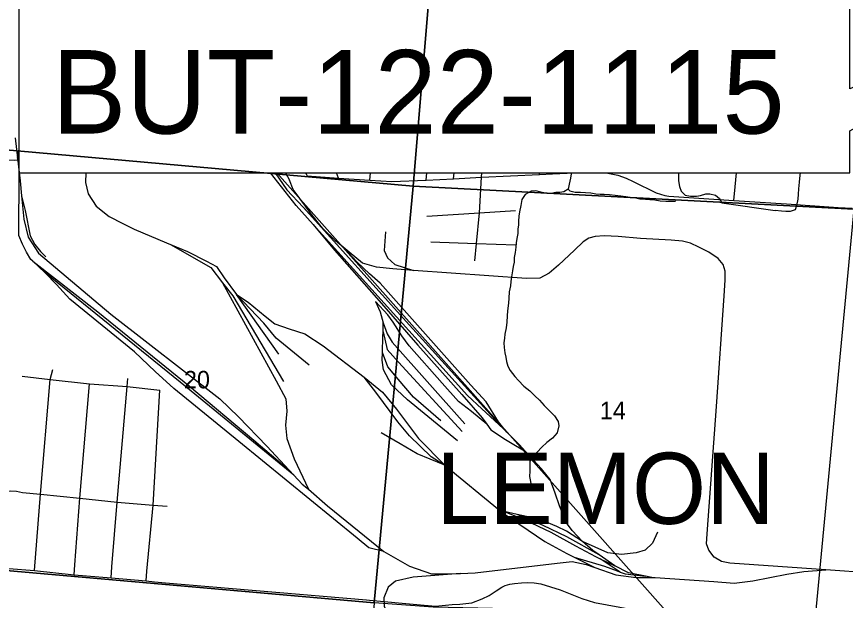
# Model space of a CAD drawing. Extents: x 0 to 34, y 0 to 22.
# Drawn here: x 17.595 to 19.579, y 15.039 to 16.438 of the extents above; entities that cross this region are included whole.
import ezdxf

# ---------------------------------------------------------------- set-up
doc = ezdxf.new("R2010")
doc.units = 0
for name, color, linetype in [('GM_X_City_Street', 7, 'Continuous'), ('GM_X_County_Road', 7, 'Continuous'), ('GM_X_Minor_River', 7, 'Continuous'), ('GM_X_Rail_Line', 7, 'Continuous'), ('GM_X_Section', 7, 'Continuous'), ('GM_X_Section_Text', 7, 'Continuous'), ('GM_X_Township_Road', 7, 'Continuous'), ('GM_X_Township_Text', 7, 'Continuous'), ('SH_Text', 7, 'Continuous')]:
    doc.layers.add(name, color=color, linetype=linetype)

msp = doc.modelspace()

# ---------------------------------------------------------------- linework, layer by layer
at = {"layer": 'GM_X_City_Street'}
for p, q in [((18.3657, 16.0508), (18.3611, 16.0631)), ((18.4407, 16.0456), (18.4422, 16.0631)), ((18.5759, 16.0462), (18.5771, 16.0631)), ((18.6414, 16.0492), (18.6427, 16.0631)), ((18.8467, 16.0595), (18.8471, 16.0631))]:
    msp.add_line(p, q, dxfattribs=at)
for points in [[(18.6925, 15.8525), (18.6965, 15.8942), (18.7033, 15.9676), (18.7082, 16.0526), (18.7093, 16.0631)], [(19.3119, 15.9972), (19.3153, 16.0297), (19.3182, 16.0631)], [(18.5773, 15.9597), (18.7033, 15.9676), (18.7898, 15.973)], [(18.5873, 15.8983), (18.6965, 15.8942), (18.7903, 15.8907)]]:
    msp.add_lwpolyline(points, dxfattribs=at)
at = {"layer": 'GM_X_County_Road'}
msp.add_line((18.2906, 16.056), (18.2881, 16.0631), dxfattribs=at)
at = {"layer": 'GM_X_Minor_River'}
for points in [[(18.9236, 16.0631), (18.9229, 16.0608), (18.9211, 16.0505), (18.918, 16.0362), (18.9158, 16.0241), (18.9053, 16.0179), (18.8958, 16.0166), (18.8863, 16.0161), (18.8752, 16.0138), (18.8645, 16.0137), (18.8505, 16.0168), (18.8385, 16.0205), (18.8267, 16.0197), (18.8131, 16.0117), (18.8048, 15.9994), (18.8021, 15.9854), (18.7994, 15.9699), (18.7979, 15.9593), (18.7965, 15.9479), (18.7966, 15.9384), (18.7951, 15.9289), (18.7948, 15.9183), (18.793, 15.9065), (18.7915, 15.8955), (18.7901, 15.8857), (18.7886, 15.8728), (18.7867, 15.861), (18.786, 15.8497), (18.7838, 15.8394), (18.7823, 15.8285), (18.78, 15.8141), (18.7782, 15.8031), (18.7775, 15.7924), (18.7748, 15.7785), (18.7736, 15.7636), (18.7725, 15.7511), (18.7701, 15.7329), (18.7693, 15.7208), (18.7689, 15.706), (18.7674, 15.6919), (18.7643, 15.6772), (18.7632, 15.6677), (18.7618, 15.6563), (18.7622, 15.6453), (18.7641, 15.6327), (18.7661, 15.622), (18.7677, 15.6116), (18.7712, 15.6005), (18.7766, 15.5897), (18.788, 15.5757), (18.7968, 15.5659), (18.8093, 15.5526), (18.8238, 15.5412), (18.836, 15.5295), (18.8468, 15.5193), (18.8582, 15.5064), (18.8708, 15.4935), (18.8826, 15.4817), (18.8913, 15.4682), (18.8933, 15.4571), (18.8894, 15.4408), (18.878, 15.4282), (18.8648, 15.4179), (18.8526, 15.4061), (18.8416, 15.3946), (18.8322, 15.385), (18.8239, 15.3731), (18.824, 15.3632), (18.824, 15.3487), (18.8232, 15.3358), (18.8252, 15.3243), (18.8271, 15.3125)], [(19.1798, 16.0631), (19.1796, 16.0596), (19.1799, 16.044), (19.1821, 16.031), (19.186, 16.0195), (19.1956, 16.0101), (19.2085, 16.0071), (19.2225, 16.0078), (19.2321, 16.0087), (19.2451, 16.0129), (19.2546, 16.013), (19.2679, 16.01), (19.2779, 16.0017), (19.2837, 15.9917)], [(19.4707, 16.0631), (19.47, 16.058), (19.4688, 16.0409), (19.4672, 16.0249), (19.466, 16.012), (19.4649, 16.0003), (19.4622, 15.9855), (19.4589, 15.975), (19.4473, 15.9707), (19.4367, 15.971), (19.4264, 15.9717), (19.4113, 15.9732)], [(18.9158, 16.0241), (18.9198, 16.0201), (18.9327, 16.0171), (18.9449, 16.0172), (18.957, 16.0164), (18.9699, 16.0153), (18.982, 16.0134), (18.9919, 16.0124), (19.0017, 16.0121), (19.0147, 16.0114), (19.0279, 16.0095), (19.0419, 16.008), (19.0533, 16.0065), (19.0639, 16.0054), (19.0741, 16.004), (19.087, 16.0014), (19.1006, 16.0002), (19.1109, 15.9999), (19.1234, 15.9984), (19.1359, 15.9966), (19.1496, 15.9954), (19.1594, 15.9955), (19.1724, 15.9952)], [(19.2837, 15.9917), (19.4113, 15.9732)]]:
    msp.add_lwpolyline(points, dxfattribs=at)
at = {"layer": 'GM_X_Rail_Line'}
for p, q in [((17.5922, 16.1472), (17.5979, 16.0984)), ((17.5979, 16.0984), (17.6011, 16.1177)), ((17.5979, 16.0984), (17.602, 16.0641)), ((18.2186, 16.0631), (19.1795, 14.9813)), ((18.2393, 16.0631), (18.2486, 16.0458)), ((18.2486, 16.0458), (18.2465, 16.0512)), ((18.2815, 15.9813), (18.3212, 15.9392)), ((17.663, 15.8244), (17.6343, 15.8519)), ((18.2228, 15.6291), (18.1217, 15.7722)), ((18.4725, 15.6823), (18.4729, 15.7041)), ((18.7651, 15.4472), (18.7603, 15.4515)), ((18.6213, 15.3623), (18.6167, 15.3652)), ((18.6213, 15.3623), (18.7509, 15.2552)), ((18.2481, 15.351), (18.2593, 15.3391)), ((18.7624, 15.2526), (18.7509, 15.2552)), ((18.7938, 15.2455), (18.7624, 15.2526)), ((18.9301, 15.1429), (18.9793, 15.118)), ((19.0277, 15.1221), (18.99, 15.1482)), ((19.0404, 15.1074), (18.9922, 15.1393)), ((18.9922, 15.1393), (19.0277, 15.1221)), ((19.116, 15.0944), (19.1008, 15.0974))]:
    msp.add_line(p, q, dxfattribs=at)
for points in [[(16.9314, 15.9596), (16.9986, 16.0519), (17.0021, 16.0564), (17.012, 16.0686), (17.0233, 16.0797), (17.0349, 16.0896), (17.05, 16.0999), (17.0647, 16.1084), (17.0791, 16.1153), (17.0938, 16.1203), (17.1078, 16.1236), (17.118, 16.1258), (17.1277, 16.1271), (17.1359, 16.1277), (17.1459, 16.1274), (17.1551, 16.1271), (17.1708, 16.1263), (17.2005, 16.124), (17.4818, 16.1001), (17.5902, 16.0938), (17.6011, 16.0941)], [(17.6343, 15.8519), (17.6299, 15.856), (17.6196, 15.8733), (17.6097, 15.8925), (17.6009, 15.9132), (17.602, 16.0641)], [(17.602, 16.0641), (17.6043, 16.0444), (17.6076, 16.0086)], [(17.7609, 16.0631), (17.7602, 16.04), (17.7671, 16.0133), (17.7863, 15.9837), (17.8174, 15.9591), (17.8499, 15.9418), (17.8671, 15.9334)], [(18.305, 15.94), (18.2645, 15.9855), (18.2035, 16.0631)], [(18.214, 16.0631), (18.2425, 16.0227), (18.2815, 15.9813)], [(18.3212, 15.9392), (18.3027, 15.9619), (18.2573, 16.0235), (18.2486, 16.0458)], [(17.6076, 16.0086), (17.6127, 15.9522), (17.623, 15.9093), (17.6482, 15.8708), (17.8213, 15.7253), (18.0817, 15.5221), (18.1266, 15.4792), (18.1942, 15.4087), (18.2481, 15.351)], [(17.6076, 16.0086), (17.6157, 15.9732), (17.6282, 15.9128), (17.6394, 15.8917), (17.6531, 15.8747), (17.6653, 15.8625)], [(18.2815, 15.9813), (18.536, 15.6987), (18.7603, 15.4515)], [(17.8671, 15.9334), (17.877, 15.9285), (17.9543, 15.8956)], [(18.7603, 15.4515), (18.7086, 15.4979), (18.6746, 15.5305), (18.305, 15.94)], [(18.305, 15.94), (18.3565, 15.8782), (18.4689, 15.7505), (18.5562, 15.6503), (18.6608, 15.5325), (18.7096, 15.4767), (18.7206, 15.4612)], [(18.3769, 15.8852), (18.3589, 15.9002), (18.3288, 15.9298), (18.3212, 15.9392)], [(18.4788, 15.9221), (18.4753, 15.8772), (18.4832, 15.8595), (18.501, 15.8442), (18.5452, 15.8297)], [(19.5326, 15.1125), (19.3024, 15.1288), (19.2827, 15.1328), (19.2654, 15.1431), (19.2521, 15.1594), (19.2467, 15.1752), (19.2482, 15.1989), (19.2704, 15.5037), (19.2891, 15.769), (19.2916, 15.8065), (19.2911, 15.8282), (19.2862, 15.844), (19.2743, 15.8583), (19.2526, 15.8736), (19.228, 15.8854), (19.2082, 15.8948), (19.1895, 15.8997), (19.1624, 15.9022), (19.0889, 15.9061), (19.0351, 15.9111), (19.0021, 15.9121), (18.9804, 15.9106), (18.9651, 15.9071), (18.9513, 15.8983), (18.9306, 15.8785), (18.8921, 15.842), (18.8704, 15.8233), (18.8477, 15.811), (18.8161, 15.8105), (18.5452, 15.8297)], [(17.9543, 15.8956), (17.9639, 15.8915), (18.0605, 15.8368), (18.0886, 15.7998)], [(17.9543, 15.8956), (18.0043, 15.8747), (18.0502, 15.8521), (18.0738, 15.8387), (18.0926, 15.8116), (18.1217, 15.7722)], [(18.7651, 15.4472), (18.7491, 15.4669), (18.719, 15.5152), (18.683, 15.5551), (18.4655, 15.7988), (18.4398, 15.8215), (18.4107, 15.8491), (18.3769, 15.8852)], [(18.5452, 15.8297), (18.496, 15.8332), (18.4571, 15.8371), (18.423, 15.847), (18.3915, 15.8731), (18.3769, 15.8852)], [(17.6343, 15.8519), (17.7898, 15.7302), (18.0092, 15.5522), (18.1636, 15.4235), (18.2481, 15.351)], [(18.4742, 15.1566), (18.4388, 15.1655), (18.4107, 15.1882), (18.1271, 15.42), (17.9717, 15.5468), (17.9269, 15.5877), (17.878, 15.6346), (17.7232, 15.7608), (17.6911, 15.7963), (17.663, 15.8244)], [(18.2593, 15.3391), (17.987, 15.5621), (17.663, 15.8244)], [(18.0886, 15.7998), (18.2169, 15.565), (18.2401, 15.5221), (18.2425, 15.4925), (18.2391, 15.459), (18.242, 15.4269), (18.2598, 15.3781), (18.2938, 15.3056)], [(18.0886, 15.7998), (18.1133, 15.7692), (18.2346, 15.564)], [(18.2958, 15.603), (18.2164, 15.6676), (18.1873, 15.7031), (18.1217, 15.7722)], [(18.1217, 15.7722), (18.1498, 15.7534), (18.1902, 15.7199), (18.2134, 15.7021), (18.2475, 15.6898), (18.2854, 15.6775), (18.3293, 15.6493), (18.4275, 15.5739)], [(18.7206, 15.4612), (18.6844, 15.492), (18.6529, 15.5157), (18.6144, 15.5596), (18.535, 15.6493), (18.5172, 15.673), (18.4965, 15.7061), (18.4842, 15.7233), (18.4547, 15.7554)], [(18.4547, 15.7554), (18.4655, 15.7307), (18.4729, 15.7041)], [(18.4729, 15.7041), (18.4827, 15.6775), (18.4946, 15.6577), (18.6687, 15.4624)], [(18.471, 15.6334), (18.4724, 15.6711), (18.4725, 15.6823)], [(18.4725, 15.6823), (18.4827, 15.64), (18.5093, 15.6099), (18.6618, 15.4437)], [(18.6504, 15.4215), (18.5311, 15.5196), (18.4926, 15.5556), (18.4733, 15.5916), (18.4704, 15.6148), (18.471, 15.6334)], [(18.611, 15.4693), (18.5454, 15.5265), (18.5084, 15.569), (18.4837, 15.599), (18.471, 15.6334)], [(18.6167, 15.3652), (18.5878, 15.3835), (18.5355, 15.4338), (18.5079, 15.4674), (18.4551, 15.5379), (18.4275, 15.5739)], [(18.4275, 15.5739), (18.4714, 15.5379), (18.5044, 15.4974), (18.5577, 15.4274), (18.6213, 15.3623)], [(18.7206, 15.4612), (18.7303, 15.4476), (18.7653, 15.4244), (18.7895, 15.4106), (18.8128, 15.397)], [(18.6167, 15.3652), (18.5542, 15.3904), (18.5133, 15.4141), (18.4684, 15.4407)], [(18.8128, 15.397), (18.7989, 15.4121), (18.7688, 15.4427), (18.7651, 15.4472)], [(18.9498, 15.1803), (18.9251, 15.2069), (18.9113, 15.2252), (18.895, 15.2656), (18.8842, 15.2962), (18.8728, 15.3293), (18.8516, 15.3549), (18.8128, 15.397)], [(18.2593, 15.3391), (18.279, 15.3179), (18.2938, 15.3056)], [(18.2938, 15.3056), (18.3397, 15.2656), (18.4742, 15.1566)], [(18.7509, 15.2552), (18.7574, 15.2498), (18.8595, 15.1808), (18.9128, 15.1517), (18.9301, 15.1429)], [(18.7624, 15.2526), (18.8122, 15.2321), (18.8738, 15.2025), (18.933, 15.1704), (18.9809, 15.1448), (18.9922, 15.1393)], [(18.99, 15.1482), (18.9128, 15.1916), (18.8561, 15.2188), (18.7938, 15.2455)], [(18.9498, 15.1803), (18.9118, 15.2055), (18.8886, 15.2168), (18.8541, 15.2311), (18.8161, 15.2405), (18.7938, 15.2455)], [(19.1298, 15.2025), (19.1175, 15.1769), (19.0997, 15.1601), (19.078, 15.1537), (19.0435, 15.1492), (19.0109, 15.1537), (18.9498, 15.1803)], [(18.99, 15.1482), (18.9749, 15.1586), (18.9498, 15.1803)], [(18.4742, 15.1566), (18.536, 15.1211), (18.5888, 15.1034), (18.6346, 15.1029), (18.6577, 15.104)], [(18.9301, 15.1429), (19.0026, 15.1211), (19.0331, 15.1103), (19.0404, 15.1074)], [(18.6577, 15.104), (18.6928, 15.1058), (18.8891, 15.129), (18.9251, 15.133), (18.9587, 15.1251), (18.9793, 15.118)], [(18.9793, 15.118), (19.0297, 15.1009), (19.078, 15.094), (19.116, 15.0944)], [(19.1008, 15.0974), (19.0598, 15.1053), (19.0277, 15.1221)], [(18.6577, 15.104), (18.5444, 15.095), (18.502, 15.0856), (18.4847, 15.0713), (18.4743, 15.0452), (18.4753, 15.0259), (18.4857, 14.9988), (18.4985, 14.9741), (18.5212, 14.9519), (18.5488, 14.9228), (18.5646, 14.8967), (18.5735, 14.8701), (18.5715, 14.8331), (18.5602, 14.804), (18.5384, 14.7749), (18.5247, 14.7611)], [(19.0404, 15.1074), (19.0519, 15.1029), (19.1008, 15.0974)], [(19.116, 15.0944), (19.1239, 15.0945), (19.264, 15.0846), (19.3133, 15.0807), (19.3572, 15.0861), (19.4386, 15.1024), (19.48, 15.1083), (19.5326, 15.1125)], [(19.924, 15.0063), (19.918, 15.0327), (19.9046, 15.0588), (19.879, 15.079), (19.8583, 15.0859), (19.841, 15.0869), (19.6428, 15.1047), (19.5326, 15.1125)]]:
    msp.add_lwpolyline(points, dxfattribs=at)
at = {"layer": 'GM_X_Section'}
for points in [[(17.6107, 17.1586), (18.6301, 17.0536), (18.5443, 16.0316), (17.5156, 16.123), (17.5304, 16.3341), (17.5798, 16.7794)], [(18.6301, 17.0536), (19.6906, 16.9733), (19.5996, 15.976), (18.5443, 16.0316)], [(17.5156, 16.123), (18.5443, 16.0316), (18.4512, 15.0336), (17.4429, 15.1223)], [(18.5443, 16.0316), (19.5996, 15.976), (19.5054, 14.9829), (19.0553, 15.0128), (18.5923, 15.0229), (18.4512, 15.0336)], [(17.4429, 15.1223), (18.4512, 15.0336), (18.3661, 13.9097), (17.5503, 13.9875), (17.3492, 14.0051)]]:
    msp.add_lwpolyline(points, close=True, dxfattribs=at)
at = {"layer": 'GM_X_Township_Road'}
for points in [[(18.2906, 16.056), (18.3657, 16.0508), (18.4407, 16.0456), (18.4936, 16.0424), (18.5759, 16.0462), (18.6414, 16.0492), (18.7082, 16.0526)], [(18.7082, 16.0526), (18.8467, 16.0595), (18.8784, 16.0607), (18.9308, 16.0635), (18.9745, 16.0635), (19.0104, 16.0624), (19.0342, 16.0574), (19.0548, 16.0507), (19.0713, 16.0428), (19.1263, 16.0151), (19.147, 16.0091), (19.1565, 16.0071), (19.3119, 15.9972)], [(19.3119, 15.9972), (19.4381, 15.9888), (19.5621, 15.9803), (19.5952, 15.9785)], [(17.6385, 15.1108), (17.653, 15.2935), (17.6759, 15.5683), (17.6822, 15.5923)], [(17.6087, 15.5762), (17.6759, 15.5683), (17.7701, 15.558), (17.8599, 15.5514), (17.9384, 15.543)], [(17.7333, 15.1008), (17.7351, 15.1244), (17.7471, 15.2841), (17.7701, 15.558)], [(17.8219, 15.0935), (17.8232, 15.1202), (17.8363, 15.2744), (17.8599, 15.5514), (17.8615, 15.571)], [(17.9054, 15.0862), (17.9075, 15.1093), (17.922, 15.2679), (17.9384, 15.543)], [(17.4497, 15.3107), (17.4662, 15.3087), (17.528, 15.3043), (17.5621, 15.3008), (17.5802, 15.302), (17.5954, 15.3014), (17.6099, 15.298), (17.653, 15.2935), (17.7471, 15.2841), (17.8363, 15.2744), (17.922, 15.2679), (17.9559, 15.2649)], [(17.4364, 15.1287), (17.5144, 15.121), (17.6385, 15.1108), (17.7333, 15.1008), (17.8219, 15.0935), (17.9054, 15.0862), (17.9256, 15.0841), (17.952, 15.0818), (18.4326, 15.0409)], [(18.4326, 15.0409), (18.4405, 15.0402), (18.5538, 15.0295), (18.5979, 15.026), (18.6377, 15.0295), (18.6564, 15.0306), (18.6848, 15.0336), (18.7095, 15.043), (18.7266, 15.0515), (18.7433, 15.0627), (18.7568, 15.0712), (18.7647, 15.0752), (18.7762, 15.0785), (18.7871, 15.0801), (18.8042, 15.0818), (18.8193, 15.0827), (18.8344, 15.0818), (18.8505, 15.0791), (18.8964, 15.0647), (18.9487, 15.0439), (18.9785, 15.0345), (19.0698, 15.0174), (19.217, 15.0087), (19.2952, 15.0031)]]:
    msp.add_lwpolyline(points, dxfattribs=at)
at = {"layer": 'SH_Text'}
msp.add_lwpolyline([(19.5901, 16.4662), (17.6011, 16.4662), (17.6011, 16.0631), (19.5901, 16.0631), (19.5901, 16.1639), (20.4399, 16.63), (19.5901, 16.2646)], close=True, dxfattribs=at)

# ---------------------------------------------------------------- texts
at = {"layer": 'GM_X_Section_Text'}
for s, p in [('20', (17.996, 15.5472)), ('14', (18.9914, 15.4734))]:
    msp.add_text(s, height=0.04186, rotation=0, dxfattribs=at).set_placement(p)
at = {"layer": 'GM_X_Township_Text'}
msp.add_text('LEMON', height=0.17045, rotation=0, dxfattribs=at).set_placement((18.5998, 15.2226))
at = {"layer": 'SH_Text'}
msp.add_text('BUT-122-1115', height=0.2, dxfattribs=at).set_placement((17.6795, 16.1574))

doc.saveas('drawing.dxf')
